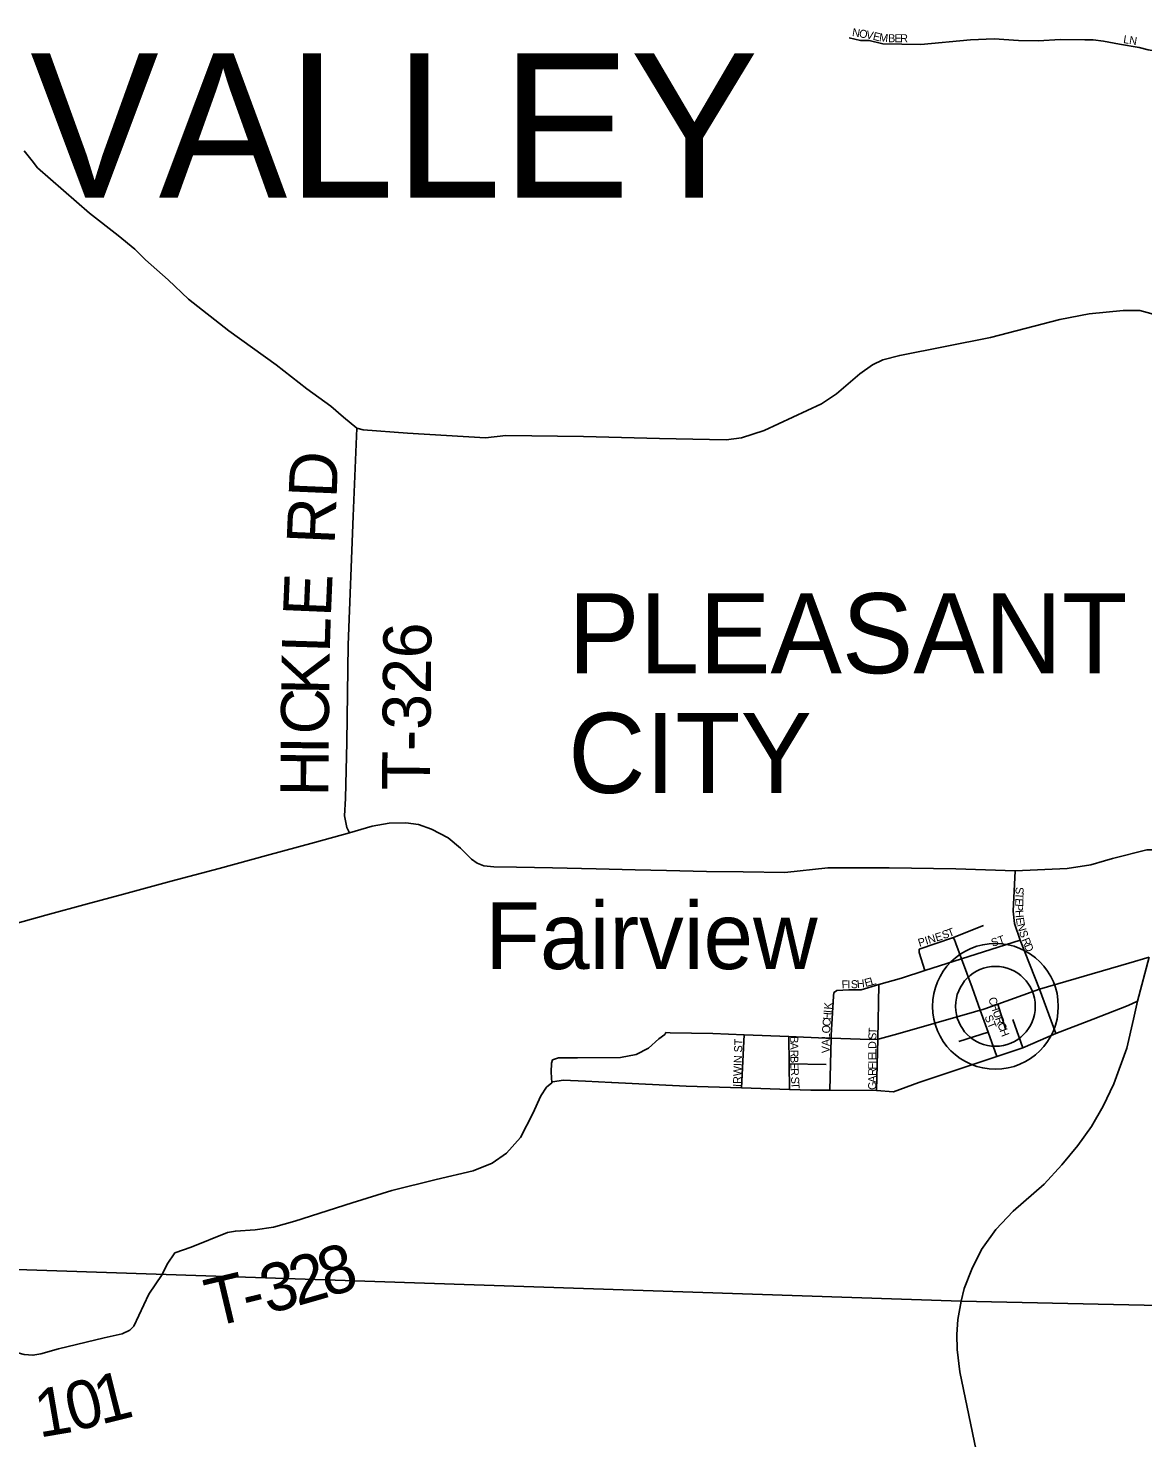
# Model space of a CAD drawing. Extents: x -22 to 431, y -18 to 160.
# Drawn here: x 322.427 to 323.745, y 156.71 to 158.378 of the extents above; entities that cross this region are included whole.
import ezdxf

# ---------------------------------------------------------------- set-up
doc = ezdxf.new("R2010")
doc.units = 0
for name, color, linetype in [('GM_X_Adjacent_County', 7, 'Continuous'), ('GM_X_Adjacent_County_Text', 7, 'Continuous'), ('GM_X_City_Street_Text', 7, 'Continuous'), ('GM_X_County_Road_Text', 7, 'Continuous'), ('GM_X_County_ROW', 7, 'Continuous'), ('GM_X_County_Subdivision', 7, 'Continuous'), ('GM_X_Interstate_Location', 7, 'Continuous'), ('GM_X_Major_River_Text', 7, 'Continuous'), ('GM_X_Minor_River_Text', 7, 'Continuous'), ('GM_X_Township_Road', 7, 'Continuous'), ('GM_X_Township_ROW', 7, 'Continuous')]:
    doc.layers.add(name, color=color, linetype=linetype)

msp = doc.modelspace()

# ---------------------------------------------------------------- linework, layer by layer
at = {"layer": 'GM_X_Adjacent_County_Text'}
for points in [[(323.5664, 157.2207), (323.5739, 157.2234), (323.6231, 157.241), (323.729, 157.2718), (323.7529, 157.2787)], [(323.1812, 157.1899), (323.1861, 157.1895), (323.2367, 157.1885), (323.2736, 157.1871), (323.3265, 157.1849), (323.3703, 157.1832), (323.3767, 157.183), (323.4224, 157.1814), (323.4317, 157.182), (323.4337, 157.1821), (323.4557, 157.1883), (323.5462, 157.2141), (323.5531, 157.2161), (323.5559, 157.2169), (323.5664, 157.2207)]]:
    msp.add_lwpolyline(points, dxfattribs=at)
at = {"layer": 'GM_X_County_ROW'}
for points in [[(322.4037, 157.3162), (322.4475, 157.3285), (322.497, 157.342), (322.5393, 157.3535), (322.5959, 157.3686), (322.6526, 157.3837), (322.7085, 157.3992), (322.7652, 157.4146), (322.8067, 157.4258), (322.8335, 157.4337), (322.8536, 157.4373), (322.8733, 157.4379), (322.8884, 157.4358), (322.9037, 157.4303), (322.9235, 157.4199), (322.938, 157.408), (322.9511, 157.3949), (322.958, 157.39), (322.9656, 157.3871), (322.9777, 157.3857), (323.0043, 157.3852), (323.0471, 157.3846), (323.0986, 157.3833), (323.1449, 157.382), (323.182, 157.3813), (323.229, 157.3803), (323.2726, 157.3797), (323.3219, 157.3792), (323.3726, 157.3847), (323.4454, 157.3847), (323.5241, 157.3832), (323.5942, 157.381), (323.6558, 157.3836), (323.684, 157.3882), (323.7001, 157.3927)], [(323.7001, 157.3927), (323.7096, 157.3954), (323.7502, 157.4059), (323.7686, 157.4059)], [(323.5305, 156.8719), (323.5342, 156.8871), (323.5432, 156.9098), (323.5546, 156.9331), (323.5716, 156.9568), (323.592, 156.9786), (323.6286, 157.0104), (323.6494, 157.0332), (323.6684, 157.056), (323.6845, 157.0787), (323.6984, 157.1028), (323.7111, 157.129), (323.7265, 157.1712), (323.7343, 157.2057), (323.7391, 157.2267), (323.7529, 157.2787)], [(323.5546, 156.6648), (323.5287, 156.7885), (323.5256, 156.8148), (323.5253, 156.8326), (323.5267, 156.8501), (323.5305, 156.8719)]]:
    msp.add_lwpolyline(points, dxfattribs=at)
at = {"layer": 'GM_X_Major_River_Text'}
for p, q in [((322.2979, 156.9132), (323.5305, 156.8719)), ((323.5305, 156.8719), (323.9653, 156.8628))]:
    msp.add_line(p, q, dxfattribs=at)
at = {"layer": 'GM_X_Minor_River_Text'}
for points in [[(322.4217, 158.2325), (322.4313, 158.221), (322.4377, 158.2126), (322.4993, 158.1588), (322.533, 158.1326), (322.5528, 158.1165), (322.5655, 158.1038), (322.5924, 158.08), (322.6163, 158.0574), (322.6642, 158.0197), (322.72, 157.9796), (322.7563, 157.9512), (322.7847, 157.9308), (322.7997, 157.9177), (322.8154, 157.9046), (322.8229, 157.9027), (322.8754, 157.8986), (322.9678, 157.893), (322.9916, 157.8958), (323.0837, 157.8947), (323.1735, 157.8925), (323.2524, 157.8908), (323.2706, 157.8933), (323.2975, 157.902), (323.3654, 157.9334), (323.3829, 157.9454), (323.4104, 157.9689), (323.4256, 157.9797), (323.4378, 157.9856), (323.4578, 157.9907), (323.5653, 158.0118), (323.6472, 158.0333), (323.6819, 158.0397), (323.722, 158.044), (323.7418, 158.044), (323.7664, 158.0371)], [(322.8067, 157.4258), (322.8035, 157.4323), (322.801, 157.446), (322.802, 157.4664), (322.8035, 157.5331), (322.8052, 157.6482), (322.8112, 157.8005), (322.8154, 157.9046)], [(323.1173, 157.1308), (323.205, 157.1264), (323.2707, 157.1243), (323.3273, 157.1225), (323.3526, 157.1216), (323.3752, 157.1215), (323.4303, 157.1213), (323.4503, 157.1197), (323.4803, 157.1308), (323.5726, 157.1615), (323.6035, 157.1718), (323.6424, 157.1885), (323.6865, 157.2057), (323.728, 157.2215), (323.7391, 157.2267)], [(323.583, 157.194), (323.5739, 157.2234)], [(323.0468, 157.1574), (323.054, 157.1596), (323.0767, 157.1597), (323.1276, 157.1603), (323.1458, 157.1638), (323.1606, 157.1712), (323.1728, 157.1821), (323.1797, 157.1873), (323.1812, 157.1899)], [(323.5278, 157.1792), (323.5624, 157.19)], [(323.0462, 157.1303), (323.0455, 157.143), (323.0456, 157.1533), (323.0468, 157.1574)], [(323.3269, 157.1526), (323.3707, 157.1519)], [(322.5851, 156.9036), (322.5909, 156.9156), (322.6003, 156.9292), (322.6195, 156.9358), (322.6624, 156.9531), (322.6718, 156.9549), (322.6953, 156.9562), (322.7168, 156.9593), (322.7422, 156.9666), (322.81, 156.9882), (322.857, 157.0028), (322.9093, 157.0158), (322.9532, 157.0263), (322.9755, 157.0351), (322.9927, 157.047), (323.0091, 157.0654), (323.0238, 157.094), (323.0331, 157.1148), (323.04, 157.1249), (323.0462, 157.1303)], [(323.0462, 157.1303), (323.0473, 157.1313), (323.0597, 157.1334), (323.0862, 157.1323), (323.1169, 157.1308), (323.1173, 157.1308)], [(322.5851, 156.9036), (322.5694, 156.8801), (322.5574, 156.8548), (322.5516, 156.8424), (322.5467, 156.8378), (322.5379, 156.8334), (322.5167, 156.8287), (322.4625, 156.8155), (322.4417, 156.8097), (322.4322, 156.8079), (322.422, 156.8087), (322.4084, 156.8123), (322.3953, 156.8192), (322.3798, 156.8251), (322.3659, 156.8278), (322.3352, 156.8285), (322.2962, 156.8293)]]:
    msp.add_lwpolyline(points, dxfattribs=at)
at = {"layer": 'GM_X_Township_Road'}
for radius in [0.0744, 0.0472]:
    msp.add_circle((323.571, 157.2207), radius, dxfattribs=at)
at = {"layer": 'GM_X_Township_ROW'}
for points in [[(323.3981, 158.3662), (323.4113, 158.3633), (323.4216, 158.3633), (323.4378, 158.3594), (323.4828, 158.3584), (323.5416, 158.3638), (323.5695, 158.3652), (323.5984, 158.3633), (323.6214, 158.3628), (323.6479, 158.3643), (323.6768, 158.3638), (323.6866, 158.3638), (323.6988, 158.3623), (323.7179, 158.3589), (323.741, 158.355), (323.7517, 158.352), (323.7679, 158.3496), (323.785, 158.352), (323.8032, 158.3569), (323.8227, 158.3569), (323.8399, 158.355)], [(323.6424, 157.1885), (323.6231, 157.241), (323.6001, 157.2991), (323.5937, 157.3188), (323.592, 157.3333), (323.5942, 157.381)], [(323.4806, 157.2884), (323.5204, 157.3019), (323.5568, 157.3163)], [(323.3807, 157.2376), (323.3834, 157.2395), (323.3977, 157.2401), (323.4121, 157.2403), (323.4332, 157.2464), (323.4598, 157.2541), (323.4873, 157.263), (323.5309, 157.2769), (323.6001, 157.2991)], [(323.5726, 157.1615), (323.5624, 157.19), (323.5531, 157.2161), (323.5435, 157.2429), (323.5309, 157.2769), (323.5241, 157.2951), (323.5223, 157.3004), (323.5204, 157.3019)], [(323.4873, 157.263), (323.4806, 157.2842), (323.4806, 157.2884)], [(323.4303, 157.1213), (323.4317, 157.182), (323.4332, 157.2464)], [(323.3752, 157.1215), (323.3767, 157.183), (323.3767, 157.1865), (323.3795, 157.2327), (323.38, 157.2369), (323.3807, 157.2376)], [(323.6035, 157.1718), (323.5914, 157.2052)], [(323.2707, 157.1243), (323.2736, 157.1871)], [(323.3273, 157.1225), (323.3269, 157.1526), (323.3265, 157.1849)]]:
    msp.add_lwpolyline(points, dxfattribs=at)

# ---------------------------------------------------------------- texts
at = {"layer": 'GM_X_Adjacent_County'}
msp.add_text('Fairview', height=0.07891, rotation=0, dxfattribs=at).set_placement((322.9677, 157.2648))
at = {"layer": 'GM_X_City_Street_Text'}
for s, height, rotation, p in [('RD', 0.05682, 87.5541, (322.7891, 157.7664)), ('E', 0.0568, 87.5307, (322.7847, 157.6808)), ('L', 0.0568, 88.2255, (322.7834, 157.6385)), ('T-326', 0.05682, 89.4377, (322.9019, 157.476)), ('K', 0.0568, 89.1803, (322.7827, 157.5887)), ('C', 0.0568, 89.4692, (322.7823, 157.5421)), ('I', 0.0568, 89.4733, (322.7821, 157.5188)), ('H', 0.0568, 89.4681, (322.7816, 157.4688)), ('2', 0.0568, 16.0173, (322.7449, 156.866)), ('8', 0.0568, 17.24, (322.7799, 156.876)), ('3', 0.0568, 14.7471, (322.7098, 156.8567)), ('T', 0.0568, 13.37, (322.6443, 156.841)), ('-', 0.0568, 13.751, (322.6861, 156.8509)), ('0', 0.0568, 14.1375, (322.4788, 156.7173)), ('1', 0.0568, 14.1395, (322.5127, 156.7258)), ('1', 0.0568, 9.6725, (322.4396, 156.7104))]:
    msp.add_text(s, height=height, rotation=rotation, dxfattribs=at).set_placement(p)
at = {"layer": 'GM_X_County_Road_Text'}
msp.add_text('VALLEY', height=0.17045, rotation=0, dxfattribs=at).set_placement((322.4291, 158.1774))
at = {"layer": 'GM_X_County_Subdivision'}
for s, rotation, p in [('N', 350.5485, (323.401, 158.3686)), ('O', 350.5522, (323.4092, 158.3672)), ('V', 348.6043, (323.4174, 158.3659)), ('E', 346.7853, (323.4254, 158.3642)), ('M', 352.7011, (323.433, 158.3625)), ('B', 359.5072, (323.4441, 158.3612)), ('E', 0.0148, (323.4517, 158.3611)), ('R', 0, (323.4584, 158.3611)), ('LN', 351.0271, (323.7218, 158.3603)), ('S', 268.6611, (323.5949, 157.3619)), ('E', 268.6699, (323.5946, 157.3486)), ('T', 268.6699, (323.5948, 157.3552)), ('P', 268.6879, (323.5944, 157.3419)), ('H', 274.5082, (323.5943, 157.3342)), ('E', 278.9601, (323.5951, 157.3251)), ('PINE', 17.2398, (323.4811, 157.291)), ('S', 17.6229, (323.5094, 157.3002)), ('T', 20.6787, (323.5163, 157.3024)), ('N', 286.1201, (323.5964, 157.3172)), ('S', 287.6079, (323.5988, 157.309)), ('ST', 18.4328, (323.5677, 157.291)), ('R', 291.419, (323.6018, 157.2996)), ('D', 292.2267, (323.6046, 157.2925)), ('F', 0.9425, (323.3891, 157.2419)), ('I', 0.9447, (323.3958, 157.2421)), ('S', 0.9425, (323.4, 157.2421)), ('H', 6.3459, (323.4076, 157.2423)), ('E', 14.8242, (323.4174, 157.2435)), ('L', 15.6392, (323.424, 157.2452)), ('K', 85.142, (323.3774, 157.2166)), ('C', 286.676, (323.5625, 157.23)), ('H', 288.2456, (323.5647, 157.2225)), ('H', 85.1202, (323.3764, 157.2042)), ('I', 85.1473, (323.3771, 157.2125)), ('ST', 291.8039, (323.5579, 157.2083)), ('U', 290.7337, (323.5675, 157.2142)), ('R', 290.701, (323.5704, 157.2064)), ('O', 85.8217, (323.3751, 157.1884)), ('C', 85.1375, (323.3757, 157.1967)), ('T', 86.6648, (323.4303, 157.1876)), ('C', 290.701, (323.5731, 157.1994)), ('H', 290.6852, (323.5757, 157.1924)), ('IRWIN ST', 88.1232, (323.2699, 157.1253)), ('B', 270.1457, (323.3282, 157.1853)), ('A', 270.1311, (323.3283, 157.1778)), ('A', 89.6887, (323.375, 157.1736)), ('L', 88.825, (323.375, 157.1819)), ('S', 87.4309, (323.43, 157.181)), ('D', 89.9253, (323.43, 157.1703)), ('R', 270.1426, (323.3283, 157.1694)), ('B', 270.1457, (323.3283, 157.1619)), ('V', 89.694, (323.3749, 157.1653)), ('L', 89.914, (323.43, 157.1636)), ('E', 89.914, (323.43, 157.1569)), ('E', 272.1773, (323.3283, 157.1541)), ('R', 273.0512, (323.3286, 157.1473)), ('I', 89.9126, (323.43, 157.1528)), ('F', 89.914, (323.43, 157.1461)), ('R', 89.9029, (323.4299, 157.1386)), ('S', 273.2806, (323.3291, 157.1372)), ('T', 273.2526, (323.3295, 157.1306)), ('G', 89.9126, (323.4299, 157.1219)), ('A', 89.9253, (323.4299, 157.1303))]:
    msp.add_text(s, height=0.00947, rotation=rotation, dxfattribs=at).set_placement(p)
at = {"layer": 'GM_X_Interstate_Location'}
for s, p in [('PLEASANT', (323.0655, 157.6147)), ('CITY', (323.0655, 157.4731))]:
    msp.add_text(s, height=0.0947, rotation=0, dxfattribs=at).set_placement(p)

doc.saveas('drawing.dxf')
